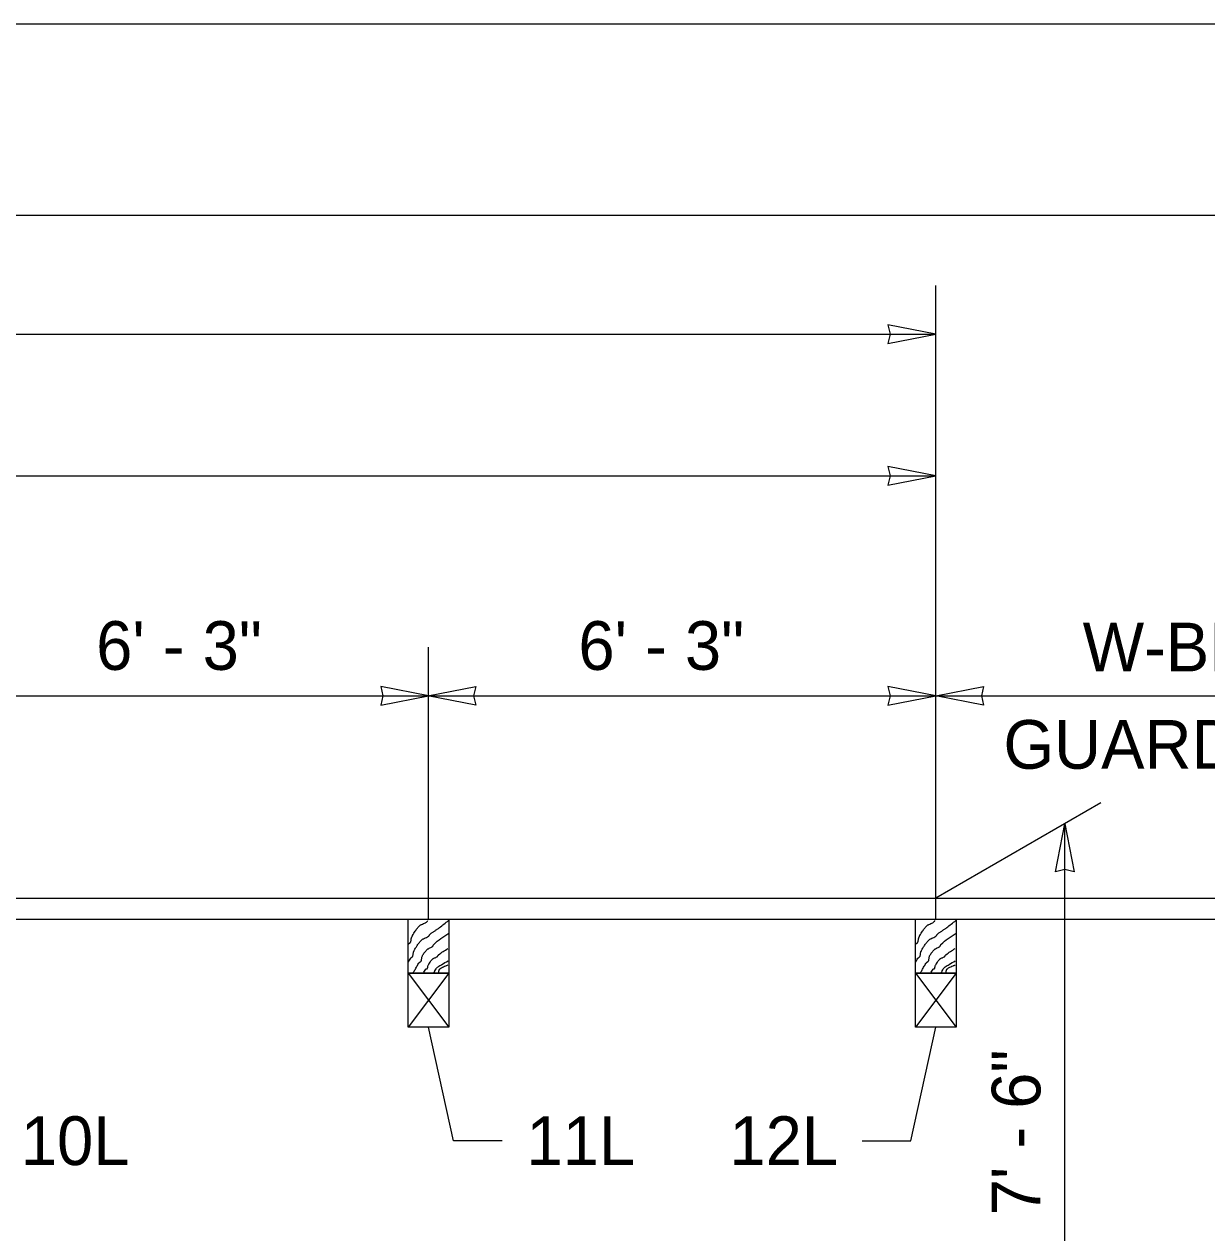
# Model space of a CAD drawing. Extents: x 1312564.2 to 1312581.5, y 1207298.4 to 1207352.6.
# Drawn here: x 1312571.742 to 1312573.678, y 1207307.442 to 1207309.421 of the extents above; entities that cross this region are included whole.
import ezdxf

# ---------------------------------------------------------------- set-up
doc = ezdxf.new("R2010")
doc.units = 0
for name, color, linetype in [('Level 1', 7, 'Continuous'), ('Level 13', 7, 'Continuous'), ('Level 14', 7, 'Continuous'), ('Level 15', 7, 'Continuous'), ('Level 2', 7, 'Continuous'), ('Level 20', 7, 'Continuous')]:
    doc.layers.add(name, color=color, linetype=linetype)

msp = doc.modelspace()

# ---------------------------------------------------------------- linework, layer by layer
at = {"layer": 'Level 1'}
msp.add_line((1312565.4154872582, 1207309.1084171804), (1312581.1654872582, 1207309.1084171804), dxfattribs=at)
at = {"layer": 'Level 13'}
for points in [[(1312572.3705385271, 1207307.8847193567), (1312572.3745098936, 1207307.891472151), (1312572.375124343, 1207307.8921798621), (1312572.3758998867, 1207307.8927569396), (1312572.3766813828, 1207307.8933288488), (1312572.377313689, 1207307.8940210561), (1312572.377809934, 1207307.8950000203), (1312572.3781402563, 1207307.8960507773), (1312572.3785089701, 1207307.8982829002), (1312572.3788315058, 1207307.9005478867), (1312572.3792907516, 1207307.9021662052), (1312572.3795195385, 1207307.9026761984), (1312572.3822477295, 1207307.9077563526), (1312572.3852974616, 1207307.9126333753), (1312572.38875612, 1207307.917244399), (1312572.3906661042, 1207307.9194305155), (1312572.3916710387, 1207307.9204902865), (1312572.392711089, 1207307.9215265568), (1312572.3940515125, 1207307.922626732), (1312572.3955238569, 1207307.923530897), (1312572.398682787, 1207307.925001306), (1312572.4018248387, 1207307.9264380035), (1312572.40395191, 1207307.9277943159), (1312572.4045869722, 1207307.9283412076), (1312572.4052531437, 1207307.929148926), (1312572.4058191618, 1207307.930065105), (1312572.4064063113, 1207307.9309622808), (1312572.407135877, 1207307.9317129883), (1312572.4106993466, 1207307.9342390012), (1312572.4143556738, 1207307.936649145), (1312572.4180012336, 1207307.939077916), (1312572.421532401, 1207307.9416598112), (1312572.4364246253, 1207307.953364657)], [(1312572.3705385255, 1207307.9137539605), (1312572.3711860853, 1207307.9148486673), (1312572.3714634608, 1207307.9152268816), (1312572.3718003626, 1207307.9155567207), (1312572.372575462, 1207307.9161339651), (1312572.3733568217, 1207307.9167057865), (1312572.3737015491, 1207307.9170288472), (1312572.3739898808, 1207307.9173975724), (1312572.37448738, 1207307.918375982), (1312572.374818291, 1207307.9194264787), (1312572.3751868, 1207307.9216586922), (1312572.3755083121, 1207307.9239241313), (1312572.3757804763, 1207307.9250161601), (1312572.3761957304, 1207307.9260527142), (1312572.3768531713, 1207307.9273378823), (1312572.3775279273, 1207307.928612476), (1312572.3819995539, 1207307.935993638), (1312572.3854614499, 1207307.9406026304), (1312572.3873621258, 1207307.9427945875), (1312572.3883586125, 1207307.94385966), (1312572.3893872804, 1207307.944903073), (1312572.3907398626, 1207307.945985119), (1312572.3922648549, 1207307.9468307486), (1312572.3955626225, 1207307.948154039), (1312572.3987416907, 1207307.9495555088), (1312572.4001183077, 1207307.950498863), (1312572.401263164, 1207307.9517177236), (1312572.402354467, 1207307.953297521)], [(1312573.2012740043, 1207307.8847193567), (1312573.2052453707, 1207307.891472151), (1312573.2058598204, 1207307.8921798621), (1312573.206635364, 1207307.8927569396), (1312573.2074168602, 1207307.8933288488), (1312573.2080491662, 1207307.8940210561), (1312573.2085454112, 1207307.8950000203), (1312573.2088757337, 1207307.8960507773), (1312573.2092444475, 1207307.8982829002), (1312573.2095669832, 1207307.9005478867), (1312573.2100262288, 1207307.9021662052), (1312573.210255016, 1207307.9026761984), (1312573.2129832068, 1207307.9077563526), (1312573.216032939, 1207307.9126333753), (1312573.2194915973, 1207307.917244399), (1312573.2214015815, 1207307.9194305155), (1312573.222406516, 1207307.9204902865), (1312573.2234465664, 1207307.9215265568), (1312573.22478699, 1207307.922626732), (1312573.226259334, 1207307.923530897), (1312573.2294182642, 1207307.925001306), (1312573.2325603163, 1207307.9264380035), (1312573.2346873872, 1207307.9277943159), (1312573.2353224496, 1207307.9283412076), (1312573.2359886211, 1207307.929148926), (1312573.2365546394, 1207307.930065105), (1312573.2371417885, 1207307.9309622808), (1312573.2378713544, 1207307.9317129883), (1312573.241434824, 1207307.9342390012), (1312573.245091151, 1207307.936649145), (1312573.2487367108, 1207307.939077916), (1312573.2522678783, 1207307.9416598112), (1312573.2671601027, 1207307.953364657)], [(1312573.201274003, 1207307.9137539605), (1312573.201921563, 1207307.9148486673), (1312573.2021989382, 1207307.9152268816), (1312573.2025358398, 1207307.9155567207), (1312573.2033109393, 1207307.9161339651), (1312573.2040922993, 1207307.9167057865), (1312573.2044370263, 1207307.9170288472), (1312573.2047253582, 1207307.9173975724), (1312573.2052228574, 1207307.918375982), (1312573.2055537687, 1207307.9194264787), (1312573.2059222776, 1207307.9216586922), (1312573.2062437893, 1207307.9239241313), (1312573.2065159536, 1207307.9250161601), (1312573.2069312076, 1207307.9260527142), (1312573.2075886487, 1207307.9273378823), (1312573.208263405, 1207307.928612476), (1312573.2127350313, 1207307.935993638), (1312573.2161969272, 1207307.9406026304), (1312573.2180976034, 1207307.9427945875), (1312573.2190940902, 1207307.94385966), (1312573.220122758, 1207307.944903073), (1312573.22147534, 1207307.945985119), (1312573.223000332, 1207307.9468307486), (1312573.2262981, 1207307.948154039), (1312573.2294771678, 1207307.9495555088), (1312573.2308537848, 1207307.950498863), (1312573.231998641, 1207307.9517177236), (1312573.2330899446, 1207307.953297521)], [(1312572.3785139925, 1207307.8672168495), (1312572.3812686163, 1207307.8723490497), (1312572.3829368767, 1207307.8753710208), (1312572.3846655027, 1207307.8783604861), (1312572.3864358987, 1207307.8813239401), (1312572.388229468, 1207307.8842678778), (1312572.3885123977, 1207307.884612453), (1312572.3888703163, 1207307.884886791), (1312572.3897133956, 1207307.885316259), (1312572.3905632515, 1207307.885739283), (1312572.3912244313, 1207307.8863388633), (1312572.391532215, 1207307.8868556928), (1312572.391786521, 1207307.8873979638), (1312572.3921640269, 1207307.8885452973), (1312572.3925999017, 1207307.890996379), (1312572.393001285, 1207307.893475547), (1312572.393561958, 1207307.8952230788), (1312572.393837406, 1207307.8957662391), (1312572.3954116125, 1207307.8983591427), (1312572.397141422, 1207307.9008547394), (1312572.399039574, 1207307.9032326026), (1312572.4011188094, 1207307.9054723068), (1312572.4022092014, 1207307.906389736), (1312572.4034186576, 1207307.9071515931), (1312572.4060287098, 1207307.9084129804), (1312572.408616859, 1207307.9096652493), (1312572.4097989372, 1207307.910415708), (1312572.4108509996, 1207307.9113171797), (1312572.4112330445, 1207307.9119323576), (1312572.4114778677, 1207307.9126612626), (1312572.4117438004, 1207307.9133715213), (1312572.4121891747, 1207307.9139307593), (1312572.4370145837, 1207307.9324948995)], [(1312573.2092494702, 1207307.8672168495), (1312573.2120040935, 1207307.8723490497), (1312573.2136723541, 1207307.8753710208), (1312573.2154009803, 1207307.8783604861), (1312573.2171713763, 1207307.8813239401), (1312573.2189649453, 1207307.8842678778), (1312573.219247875, 1207307.884612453), (1312573.2196057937, 1207307.884886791), (1312573.2204488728, 1207307.885316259), (1312573.221298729, 1207307.885739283), (1312573.2219599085, 1207307.8863388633), (1312573.2222676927, 1207307.8868556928), (1312573.2225219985, 1207307.8873979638), (1312573.2228995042, 1207307.8885452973), (1312573.223335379, 1207307.890996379), (1312573.223736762, 1207307.893475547), (1312573.2242974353, 1207307.8952230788), (1312573.2245728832, 1207307.8957662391), (1312573.22614709, 1207307.8983591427), (1312573.2278768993, 1207307.9008547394), (1312573.2297750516, 1207307.9032326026), (1312573.2318542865, 1207307.9054723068), (1312573.2329446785, 1207307.906389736), (1312573.234154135, 1207307.9071515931), (1312573.236764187, 1207307.9084129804), (1312573.2393523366, 1207307.9096652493), (1312573.2405344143, 1207307.910415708), (1312573.2415864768, 1207307.9113171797), (1312573.2419685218, 1207307.9119323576), (1312573.2422133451, 1207307.9126612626), (1312573.2424792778, 1207307.9133715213), (1312573.2429246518, 1207307.9139307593), (1312573.2677500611, 1207307.9324948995)], [(1312572.395383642, 1207307.8672168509), (1312572.3993067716, 1207307.8737669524), (1312572.3995254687, 1207307.8740012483), (1312572.39981993, 1207307.874147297), (1312572.4005369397, 1207307.8742906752), (1312572.4012593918, 1207307.8744291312), (1312572.4017888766, 1207307.8747947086), (1312572.40192999, 1207307.8750384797), (1312572.4020432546, 1207307.8752945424), (1312572.4022013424, 1207307.875837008), (1312572.402349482, 1207307.8769975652), (1312572.4024749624, 1207307.8781718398), (1312572.4026047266, 1207307.8787314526), (1312572.402819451, 1207307.879255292), (1312572.4036161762, 1207307.8807279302), (1312572.4044412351, 1207307.8821904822), (1312572.4062161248, 1207307.8850514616), (1312572.4093395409, 1207307.8890556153), (1312572.4099298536, 1207307.889675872), (1312572.4105434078, 1207307.8902798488), (1312572.4114092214, 1207307.8909680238), (1312572.4123641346, 1207307.891518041), (1312572.41441809, 1207307.8923802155), (1312572.4164589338, 1207307.8932195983), (1312572.4178327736, 1207307.8940466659), (1312572.4180402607, 1207307.8942130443), (1312572.4182403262, 1207307.8943894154), (1312572.418771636, 1207307.8950470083), (1312572.4192132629, 1207307.8958028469), (1312572.4196782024, 1207307.8965359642), (1312572.42027945, 1207307.8971253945), (1312572.4354167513, 1207307.907342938)], [(1312573.2261191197, 1207307.8672168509), (1312573.2300422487, 1207307.8737669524), (1312573.230260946, 1207307.8740012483), (1312573.2305554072, 1207307.874147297), (1312573.2312724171, 1207307.8742906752), (1312573.231994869, 1207307.8744291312), (1312573.232524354, 1207307.8747947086), (1312573.2326654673, 1207307.8750384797), (1312573.232778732, 1207307.8752945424), (1312573.2329368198, 1207307.875837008), (1312573.2330849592, 1207307.8769975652), (1312573.2332104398, 1207307.8781718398), (1312573.2333402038, 1207307.8787314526), (1312573.2335549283, 1207307.879255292), (1312573.2343516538, 1207307.8807279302), (1312573.2351767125, 1207307.8821904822), (1312573.2369516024, 1207307.8850514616), (1312573.240075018, 1207307.8890556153), (1312573.240665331, 1207307.889675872), (1312573.2412788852, 1207307.8902798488), (1312573.2421446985, 1207307.8909680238), (1312573.243099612, 1207307.891518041), (1312573.245153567, 1207307.8923802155), (1312573.247194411, 1207307.8932195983), (1312573.2485682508, 1207307.8940466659), (1312573.248775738, 1207307.8942130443), (1312573.2489758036, 1207307.8943894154), (1312573.2495071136, 1207307.8950470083), (1312573.2499487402, 1207307.8958028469), (1312573.2504136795, 1207307.8965359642), (1312573.2510149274, 1207307.8971253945), (1312573.2661522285, 1207307.907342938)], [(1312572.4122130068, 1207307.8672168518), (1312572.413608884, 1207307.869551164), (1312572.4139176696, 1207307.8700851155), (1312572.4142171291, 1207307.8706325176), (1312572.415997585, 1207307.8739873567), (1312572.4174041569, 1207307.8760133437), (1312572.4192258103, 1207307.877588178), (1312572.425366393, 1207307.8813016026), (1312572.435587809, 1207307.8874828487)], [(1312572.4201862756, 1207307.8672168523), (1312572.4204525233, 1207307.8689926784), (1312572.4207631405, 1207307.8707328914), (1312572.4212449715, 1207307.8723356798), (1312572.4215897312, 1207307.8730537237), (1312572.4217950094, 1207307.8733863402), (1312572.4219067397, 1207307.8735453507), (1312572.4219649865, 1207307.873622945), (1312572.4219947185, 1207307.8736612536), (1312572.4220097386, 1207307.873680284), (1312572.422024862, 1207307.8736992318), (1312572.4223070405, 1207307.8740318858), (1312572.4226070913, 1207307.8743501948), (1312572.423257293, 1207307.8749466), (1312572.4247334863, 1207307.8759983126), (1312572.4281921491, 1207307.8776953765), (1312572.4319508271, 1207307.8791516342), (1312572.4338020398, 1207307.8799023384), (1312572.4355594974, 1207307.8807282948)], [(1312573.2429484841, 1207307.8672168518), (1312573.2443443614, 1207307.869551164), (1312573.2446531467, 1207307.8700851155), (1312573.2449526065, 1207307.8706325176), (1312573.2467330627, 1207307.8739873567), (1312573.2481396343, 1207307.8760133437), (1312573.2499612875, 1207307.877588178), (1312573.2561018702, 1207307.8813016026), (1312573.2663232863, 1207307.8874828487)], [(1312573.250921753, 1207307.8672168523), (1312573.251188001, 1207307.8689926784), (1312573.2514986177, 1207307.8707328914), (1312573.251980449, 1207307.8723356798), (1312573.2523252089, 1207307.8730537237), (1312573.2525304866, 1207307.8733863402), (1312573.2526422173, 1207307.8735453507), (1312573.2527004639, 1207307.873622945), (1312573.2527301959, 1207307.8736612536), (1312573.2527452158, 1207307.873680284), (1312573.252760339, 1207307.8736992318), (1312573.2530425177, 1207307.8740318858), (1312573.2533425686, 1207307.8743501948), (1312573.2539927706, 1207307.8749466), (1312573.2554689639, 1207307.8759983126), (1312573.2589276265, 1207307.8776953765), (1312573.2626863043, 1207307.8791516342), (1312573.264537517, 1207307.8799023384), (1312573.2662949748, 1207307.8807282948)]]:
    msp.add_spline(points, degree=3, dxfattribs=at)
at = {"layer": 'Level 14'}
for p, q in [((1312572.3705385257, 1207307.867216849), (1312572.4368627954, 1207307.778740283)), ((1312572.4368627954, 1207307.8672168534), (1312572.3705385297, 1207307.7787402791)), ((1312573.2012740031, 1207307.867216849), (1312573.2675982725, 1207307.778740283)), ((1312573.2675982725, 1207307.8672168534), (1312573.2012740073, 1207307.7787402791))]:
    msp.add_line(p, q, dxfattribs=at)
at = {"layer": 'Level 15'}
for p, q in [((1312573.2344361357, 1207307.9556934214), (1312573.2344361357, 1207308.9931347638)), ((1312566.2180639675, 1207308.9134061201), (1312573.2344361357, 1207308.9134061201)), ((1312568.2594130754, 1207308.6812711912), (1312573.2344361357, 1207308.6812711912)), ((1312572.4037006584, 1207307.9556934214), (1312572.4037006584, 1207308.4010699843)), ((1312571.5746473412, 1207308.3213413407), (1312572.4037006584, 1207308.3213413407)), ((1312572.40269729, 1207308.3213413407), (1312573.2344361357, 1207308.3213413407)), ((1312573.2344361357, 1207308.3213413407), (1312575.0870337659, 1207308.3213413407)), ((1312573.504706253, 1207308.1457605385), (1312573.2344361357, 1207307.989720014)), ((1312573.4455654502, 1207307.1095576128), (1312573.4455654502, 1207308.1116155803)), ((1312568.257395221, 1207307.989720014), (1312575.0870337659, 1207307.989720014)), ((1312568.2569752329, 1207307.9556253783), (1312575.0870337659, 1207307.9556253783)), ((1312572.4445014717, 1207307.5928008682), (1312572.4037006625, 1207307.778740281)), ((1312573.1936353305, 1207307.5928008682), (1312573.2344361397, 1207307.778740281)), ((1312572.5242301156, 1207307.5928008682), (1312572.4445014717, 1207307.5928008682)), ((1312573.113906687, 1207307.5928008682), (1312573.1936353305, 1207307.5928008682))]:
    msp.add_line(p, q, dxfattribs=at)
for points in [[(1312573.2344361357, 1207308.9134061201), (1312573.1560778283, 1207308.928773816), (1312573.1597054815, 1207308.9134061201), (1312573.1560778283, 1207308.898038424)], [(1312573.2344361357, 1207308.6812711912), (1312573.1560778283, 1207308.6966388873), (1312573.1597054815, 1207308.6812711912), (1312573.1560778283, 1207308.6659034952)], [(1312572.4037006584, 1207308.3213413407), (1312572.3253423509, 1207308.3367090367), (1312572.328970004, 1207308.3213413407), (1312572.3253423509, 1207308.3059736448)], [(1312572.40269729, 1207308.3213413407), (1312572.4810555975, 1207308.3367090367), (1312572.4774279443, 1207308.3213413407), (1312572.4810555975, 1207308.3059736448)], [(1312573.2344361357, 1207308.3213413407), (1312573.1560778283, 1207308.3367090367), (1312573.1597054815, 1207308.3213413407), (1312573.1560778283, 1207308.3059736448)], [(1312573.2344361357, 1207308.3213413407), (1312573.312794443, 1207308.3367090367), (1312573.3091667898, 1207308.3213413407), (1312573.312794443, 1207308.3059736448)], [(1312573.4455654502, 1207308.1116155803), (1312573.4609331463, 1207308.0332572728), (1312573.4455654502, 1207308.0368849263), (1312573.4301977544, 1207308.0332572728)], [(1312572.3705385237, 1207307.9556934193), (1312572.4368627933, 1207307.9556934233), (1312572.4368627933, 1207307.8672168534), (1312572.3705385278, 1207307.867216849)], [(1312573.201274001, 1207307.9556934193), (1312573.2675982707, 1207307.9556934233), (1312573.2675982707, 1207307.8672168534), (1312573.2012740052, 1207307.867216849)], [(1312572.3705385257, 1207307.867216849), (1312572.4368627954, 1207307.8672168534), (1312572.4368627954, 1207307.778740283), (1312572.3705385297, 1207307.7787402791)], [(1312573.2012740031, 1207307.867216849), (1312573.2675982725, 1207307.8672168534), (1312573.2675982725, 1207307.778740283), (1312573.2012740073, 1207307.7787402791)]]:
    msp.add_lwpolyline(points, close=True, dxfattribs=at)
at = {"layer": 'Level 2'}
msp.add_lwpolyline([(1312564.4779872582, 1207298.4209171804), (1312581.4779872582, 1207298.4209171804), (1312581.4779872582, 1207309.4209171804), (1312564.4779872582, 1207309.4209171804)], close=True, dxfattribs=at)

# ---------------------------------------------------------------- texts
at = {"layer": 'Level 20'}
for s, p in [('6\' - 3"', (1312571.8594148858, 1207308.3636921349)), ('6\' - 3"', (1312572.6491470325, 1207308.3636921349)), ('W-BEAM OR THRIE BEAM ', (1312573.4749488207, 1207308.3612056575)), ('GUARDRAIL (SEE CONTRACT) ', (1312573.3452091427, 1207308.2017483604)), ('10L', (1312571.7360444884, 1207307.5529365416)), ('11L', (1312572.564094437, 1207307.5529365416)), ('12L', (1312572.8964144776, 1207307.5529365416))]:
    msp.add_text(s, height=0.07972865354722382, dxfattribs=at).set_placement(p)
msp.add_text('7\' - 6"', height=0.07972865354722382, rotation=90, dxfattribs=at).set_placement((1312573.4057011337, 1207307.470575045))

doc.saveas('drawing.dxf')
